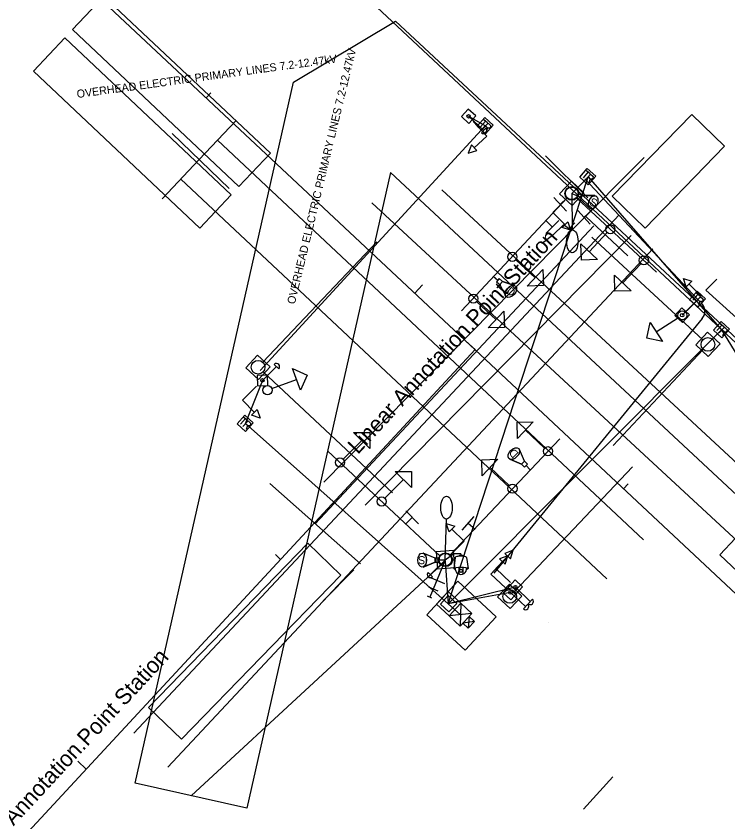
# Model space of a CAD drawing. Extents: x 1470334 to 1482043, y 378207 to 388330.
# Drawn here: x 1480096 to 1480220.4, y 379336.3 to 379477.2 of the extents above; entities that cross this region are included whole.
import ezdxf

# ---------------------------------------------------------------- set-up
doc = ezdxf.new("R2010")
doc.units = 0
for name, color, linetype in [('Default', 7, 'Continuous'), ('DR_X_Ditch', 7, 'Continuous'), ('DT_X_TIN_Hull', 7, 'Continuous'), ('GK_Visualization', 7, 'Continuous'), ('LT_X_Poles', 7, 'Continuous'), ('PM_X_Cells', 7, 'Continuous'), ('PM_X_Stop_Line', 7, 'Continuous'), ('PM_X_Surveyed_Line', 7, 'Continuous'), ('PV_X_Driveway', 7, 'Continuous'), ('PV_X_Parking_Lot', 7, 'Continuous'), ('PV_X_Steps', 7, 'Continuous'), ('RD_X_Cells', 7, 'Continuous'), ('RS_Raster1', 7, 'Continuous'), ('SV_X_Break_Lines', 7, 'Continuous'), ('SV_X_Control_Cells_Found', 7, 'Continuous'), ('SV_X_Random_Point', 7, 'Continuous'), ('SV_X_Text_Elevation', 7, 'Continuous'), ('SV_X_Text_Name', 7, 'Continuous'), ('UT_X_Gas_Cells', 7, 'Continuous'), ('UT_X_Sanitary_Cells', 7, 'Continuous'), ('UT_X_Unknown_Cells', 7, 'Continuous'), ('VG_X_Cells', 7, 'Continuous'), ('VG_X_Flower_Bed', 7, 'Continuous')]:
    doc.layers.add(name, color=color, linetype=linetype)

msp = doc.modelspace()

# ---------------------------------------------------------------- linework, layer by layer
at = {"layer": 'Default'}
for p, q in [((1479566.69, 379989.53), (1480555.97, 379063.33)), ((1480129.2, 379462.89), (1480130.02, 379463.77)), ((1480165.7, 379428.72), (1480167.07, 379430.18)), ((1480176.23, 379418.85), (1480174.77, 379420.21)), ((1480040.24, 379272.2), (1480176.23, 379418.85)), ((1480202.2, 379394.54), (1480203.02, 379395.42)), ((1480142.24, 379382.19), (1480141.36, 379383.01)), ((1480189.09, 379371.13), (1480189.09, 379371.13)), ((1480108.24, 379345.53), (1480106.77, 379346.89)), ((1480200.31, 379344.17), (1480195.21, 379338.53))]:
    msp.add_line(p, q, dxfattribs=at)
at = {"layer": 'DR_X_Ditch'}
for p, q in [((1480195.46, 379448.71), (1480215.13, 379427.66)), ((1480193.15, 379446.17), (1480193.15, 379446.17)), ((1480212.46, 379424.87), (1480215.19, 379427.6)), ((1480215.13, 379427.66), (1480215.13, 379427.66)), ((1480215.97, 379424.3), (1480179.5, 379379.76)), ((1480211.81, 379424.41), (1480207.93, 379421.93)), ((1480212.46, 379424.87), (1480212.46, 379424.87)), ((1480140.69, 379412.05), (1480145, 379413.66))]:
    msp.add_line(p, q, dxfattribs=at)
for points in [[(1480192.3, 379445.32), (1480189.82, 379442.85), (1480191.94, 379440.73)], [(1480213.31, 379425.72), (1480215.79, 379428.19), (1480213.67, 379430.32)], [(1480215.21, 379428.48), (1480214.32, 379427.49)], [(1480214.9, 379428.76), (1480215.52, 379428.21)], [(1480214.74, 379427.11), (1480215.63, 379428.11), (1480216, 379427.77), (1480216.04, 379427.73), (1480216.08, 379427.66), (1480216.09, 379427.63), (1480216.1, 379427.59), (1480216.09, 379427.52), (1480216.08, 379427.46), (1480216.04, 379427.39), (1480215.96, 379427.29), (1480215.92, 379427.27), (1480215.86, 379427.24), (1480215.78, 379427.21), (1480215.73, 379427.21), (1480215.69, 379427.22), (1480215.67, 379427.22), (1480215.64, 379427.24), (1480215.56, 379427.29), (1480215.19, 379427.62)], [(1480215.56, 379427.29), (1480215.32, 379426.59)]]:
    msp.add_lwpolyline(points, dxfattribs=at)
for points in [[(1480191.45, 379440.23), (1480192.44, 379441.22), (1480192.93, 379439.73)], [(1480214.17, 379430.81), (1480213.18, 379429.82), (1480212.68, 379431.31)], [(1480215.05, 379429.07), (1480216.54, 379427.74), (1480215.21, 379426.25), (1480213.72, 379427.58)], [(1480211.19, 379424.83), (1480212.5, 379423.6), (1480213.73, 379424.92), (1480212.42, 379426.15)], [(1480209.01, 379420.25), (1480206.25, 379420.85), (1480206.86, 379423.62)], [(1480144.3, 379415.53), (1480146.87, 379414.36), (1480145.7, 379411.79)]]:
    msp.add_lwpolyline(points, close=True, dxfattribs=at)
for centre, radius in [((1480212.48, 379424.84), 0.8), ((1480212.46, 379424.87), 0.3), ((1480139.94, 379411.77), 0.8)]:
    msp.add_circle(centre, radius, dxfattribs=at)
msp.add_arc((1480214.43, 379425.57), 2, 320.6881, 45.2385, dxfattribs=at)
at = {"layer": 'DT_X_TIN_Hull'}
for p, q in [((1480183.31, 379377.31), (1480171.52, 379374.44)), ((1480183.27, 379377.34), (1480183.27, 379377.34)), ((1480183.29, 379377.32), (1480185.89, 379374.83)), ((1480186.28, 379375.24), (1480185.5, 379374.43))]:
    msp.add_line(p, q, dxfattribs=at)
for points in [[(1480181.45, 379383.24), (1480182.46, 379382.27), (1480182.93, 379383.77)], [(1480183.33, 379376.05), (1480184.56, 379377.37), (1480183.25, 379378.6), (1480182.02, 379377.28)]]:
    msp.add_lwpolyline(points, close=True, dxfattribs=at)
msp.add_lwpolyline([(1480182.41, 379378.17), (1480179.88, 379380.59), (1480181.96, 379382.76)], dxfattribs=at)
msp.add_circle((1480183.29, 379377.32), 0.3, dxfattribs=at)
msp.add_arc((1480185.89, 379374.83), 0.56, 226.2141, 46.2138, dxfattribs=at)
at = {"layer": 'GK_Visualization'}
for points in [[(1480193.23, 379444.05), (1480195.27, 379446.24), (1480193.08, 379448.29), (1480191.03, 379446.09)], [(1480138.13, 379414.35), (1480138.19, 379412.55), (1480139.99, 379412.61), (1480139.93, 379414.41)], [(1480172.68, 379380.76), (1480172.44, 379383.75), (1480169.45, 379383.5), (1480169.69, 379380.51)], [(1480182.5, 379375.12), (1480183.71, 379376.45), (1480182.37, 379377.66), (1480181.16, 379376.33)]]:
    msp.add_lwpolyline(points, close=True, dxfattribs=at)
for centre, radius in [((1480193.15, 379446.17), 1.2), ((1480139.06, 379413.48), 0.3), ((1480171.07, 379382.13), 1.2), ((1480182.43, 379376.39), 0.3)]:
    msp.add_circle(centre, radius, dxfattribs=at)
at = {"layer": 'PM_X_Cells'}
for p, q in [((1480199.34, 379439.32), (1480196.2, 379435.96)), ((1480183.35, 379434.53), (1480186.73, 379431.4)), ((1480205.2, 379433.87), (1480202.06, 379430.51)), ((1480176.52, 379427.23), (1480179.89, 379424.11)), ((1480138.88, 379413.31), (1480138.88, 379413.31)), ((1480188.4, 379401.64), (1480185.04, 379404.78)), ((1480153.18, 379399.7), (1480156.41, 379402.97)), ((1480182.21, 379395.1), (1480178.86, 379398.25)), ((1480160.47, 379392.88), (1480163.7, 379396.15)), ((1480170.99, 379382.04), (1480170.99, 379382.04)), ((1480182.42, 379376.4), (1480182.42, 379376.4))]:
    msp.add_line(p, q, dxfattribs=at)
for points in [[(1480197.66, 379434.6), (1480194.83, 379434.5), (1480194.74, 379437.33)], [(1480188.08, 379432.87), (1480188.19, 379430.05), (1480185.37, 379429.94)], [(1480203.52, 379429.15), (1480200.69, 379429.05), (1480200.6, 379431.88)], [(1480181.25, 379425.57), (1480181.36, 379422.75), (1480178.53, 379422.64)], [(1480137.17, 379407.37), (1480138.16, 379408.36), (1480138.66, 379406.87)], [(1480183.68, 379403.32), (1480183.59, 379406.15), (1480186.41, 379406.24)], [(1480154.99, 379404.37), (1480157.81, 379404.39), (1480157.83, 379401.56)], [(1480177.49, 379396.79), (1480177.4, 379399.61), (1480180.23, 379399.7)], [(1480162.27, 379397.55), (1480165.1, 379397.57), (1480165.12, 379394.75)], [(1480172.7, 379387.98), (1480171.7, 379386.99), (1480171.21, 379388.48)], [(1480180.5, 379382.28), (1480181.53, 379381.32), (1480181.97, 379382.83)]]:
    msp.add_lwpolyline(points, close=True, dxfattribs=at)
for points in [[(1480138.03, 379412.46), (1480135.55, 379409.99), (1480137.67, 379407.86)], [(1480171.84, 379382.89), (1480174.32, 379385.36), (1480172.2, 379387.49)], [(1480181.54, 379377.22), (1480178.97, 379379.6), (1480181.01, 379381.8)]]:
    msp.add_lwpolyline(points, dxfattribs=at)
for centre in [(1480199.89, 379439.9), (1480182.76, 379435.07), (1480205.75, 379434.45), (1480175.93, 379427.77), (1480188.98, 379401.09), (1480152.62, 379399.13), (1480182.79, 379394.55), (1480159.91, 379392.31)]:
    msp.add_circle(centre, 0.8, dxfattribs=at)
at = {"layer": 'PM_X_Stop_Line'}
msp.add_line((1480193.15, 379446.17), (1480193.2, 379439.77), dxfattribs=at)
msp.add_ellipse((1480193.24, 379437.77), major_axis=(0, -2), ratio=0.5, dxfattribs=at)
at = {"layer": 'PM_X_Surveyed_Line'}
msp.add_line((1480005.18, 379622.84), (1480577.77, 379086.76), dxfattribs=at)
at = {"layer": 'PV_X_Driveway'}
for p, q in [((1480171.52, 379374.44), (1480196.02, 379449.05)), ((1480193.15, 379446.17), (1480195.93, 379448.95)), ((1480196.02, 379449.05), (1480219.33, 379422.34)), ((1480171.52, 379374.44), (1480219.33, 379422.34)), ((1480219.33, 379422.34), (1480224.91, 379413.13)), ((1480136.09, 379405.92), (1480139.1, 379413.52)), ((1480171.52, 379374.44), (1480136.04, 379405.97)), ((1480170.99, 379381.85), (1480171.52, 379374.44)), ((1480182.44, 379376.38), (1480171.52, 379374.44)), ((1480173.69, 379372.51), (1480171.52, 379374.44))]:
    msp.add_line(p, q, dxfattribs=at)
at = {"layer": 'PV_X_Parking_Lot'}
for p, q in [((1480195.95, 379449.09), (1480195.95, 379449.09)), ((1480219.33, 379422.34), (1480219.33, 379422.34)), ((1480136.04, 379405.97), (1480136.04, 379405.97))]:
    msp.add_line(p, q, dxfattribs=at)
for points in [[(1480195.87, 379450.5), (1480197.36, 379449.17), (1480196.03, 379447.68), (1480194.54, 379449.01)], [(1480219.26, 379423.76), (1480220.75, 379422.42), (1480219.41, 379420.93), (1480217.92, 379422.27)], [(1480135.96, 379407.39), (1480137.45, 379406.05), (1480136.11, 379404.56), (1480134.62, 379405.9)]]:
    msp.add_lwpolyline(points, close=True, dxfattribs=at)
for points in [[(1480196.03, 379449.91), (1480195.14, 379448.91)], [(1480195.56, 379448.54), (1480196.45, 379449.53), (1480196.82, 379449.2), (1480196.86, 379449.16), (1480196.9, 379449.09), (1480196.91, 379449.05), (1480196.92, 379449.02), (1480196.91, 379448.95), (1480196.9, 379448.89), (1480196.86, 379448.81), (1480196.78, 379448.72), (1480196.74, 379448.7), (1480196.68, 379448.66), (1480196.6, 379448.64), (1480196.55, 379448.64), (1480196.51, 379448.65), (1480196.49, 379448.65), (1480196.46, 379448.67), (1480196.38, 379448.72), (1480196.01, 379449.05)], [(1480195.72, 379450.19), (1480196.34, 379449.63)], [(1480196.38, 379448.72), (1480196.15, 379448.02)], [(1480219.42, 379423.16), (1480218.53, 379422.17)], [(1480218.95, 379421.8), (1480219.84, 379422.79), (1480220.21, 379422.45), (1480220.24, 379422.41), (1480220.28, 379422.35), (1480220.29, 379422.31), (1480220.3, 379422.27), (1480220.3, 379422.21), (1480220.29, 379422.15), (1480220.25, 379422.07), (1480220.16, 379421.98), (1480220.13, 379421.95), (1480220.07, 379421.92), (1480219.99, 379421.89), (1480219.94, 379421.9), (1480219.9, 379421.9), (1480219.88, 379421.91), (1480219.85, 379421.92), (1480219.77, 379421.98), (1480219.4, 379422.31)], [(1480219.11, 379423.44), (1480219.72, 379422.89)], [(1480219.77, 379421.98), (1480219.53, 379421.27)], [(1480136.12, 379406.79), (1480135.23, 379405.8)], [(1480135.65, 379405.43), (1480136.54, 379406.42), (1480136.91, 379406.08), (1480136.94, 379406.04), (1480136.98, 379405.98), (1480136.99, 379405.94), (1480137, 379405.9), (1480137, 379405.84), (1480136.99, 379405.78), (1480136.95, 379405.7), (1480136.86, 379405.61), (1480136.83, 379405.58), (1480136.77, 379405.55), (1480136.69, 379405.52), (1480136.64, 379405.53), (1480136.6, 379405.53), (1480136.58, 379405.54), (1480136.55, 379405.55), (1480136.47, 379405.61), (1480136.1, 379405.94)], [(1480135.81, 379407.07), (1480136.43, 379406.52)], [(1480136.47, 379405.61), (1480136.23, 379404.9)]]:
    msp.add_lwpolyline(points, dxfattribs=at)
at = {"layer": 'PV_X_Steps'}
for p, q in [((1480192.2, 379443.06), (1480190.04, 379445.43)), ((1480191.12, 379444.24), (1480192.3, 379445.32)), ((1480196.38, 379440.81), (1480194.22, 379443.18)), ((1480195.3, 379441.99), (1480196.48, 379443.07)), ((1480190.9, 379441.4), (1480188.63, 379439.15)), ((1480189.77, 379440.27), (1480188.64, 379441.41)), ((1480164.11, 379390.65), (1480166.37, 379388.38)), ((1480165.24, 379389.52), (1480164.11, 379388.39)), ((1480173.97, 379387.31), (1480176.09, 379389.71)), ((1480175.03, 379388.51), (1480176.23, 379387.45))]:
    msp.add_line(p, q, dxfattribs=at)
at = {"layer": 'RD_X_Cells'}
msp.add_line((1480170.99, 379382.04), (1480171.23, 379389.22), dxfattribs=at)
for centre in [(1480193.15, 379446.17), (1480171.04, 379382.12)]:
    msp.add_circle(centre, 1.1, dxfattribs=at)
msp.add_ellipse((1480171.24, 379391.22), major_axis=(0.01, 2), ratio=0.5, dxfattribs=at)
at = {"layer": 'RS_Raster1'}
for p, q in [((1480170.99, 379382.04), (1480168.31, 379375.58)), ((1480168.15, 379379.11), (1480170.92, 379377.96)), ((1480168.09, 379377.4), (1480169.75, 379376.71)), ((1480168.67, 379375.42), (1480167.94, 379375.73))]:
    msp.add_line(p, q, dxfattribs=at)
at = {"layer": 'SV_X_Break_Lines'}
for p, q in [((1480218.5, 379431.17), (1480216.59, 379429.25)), ((1480216.59, 379429.25), (1480241.59, 379406.51))]:
    msp.add_line(p, q, dxfattribs=at)
at = {"layer": 'SV_X_Control_Cells_Found'}
for p, q in [((1480148.26, 379388.42), (1480197.02, 379440.5)), ((1480140.34, 379395.44), (1480156.18, 379381.4))]:
    msp.add_line(p, q, dxfattribs=at)
msp.add_lwpolyline([(1480205.81, 379452.44), (1480193.1, 379439.67), (1480191.7, 379440.66), (1480189.86, 379438.85), (1480187.98, 379437.39)], dxfattribs=at)
at = {"layer": 'SV_X_Random_Point'}
for p, q in [((1480173.85, 379425.61), (1480192.3, 379445.32)), ((1480194.03, 379445.35), (1480207.94, 379432.41)), ((1480195.64, 379442.04), (1480202.97, 379435.23)), ((1480171.8, 379382.93), (1480191.04, 379403.27)), ((1480170.15, 379382.74), (1480150.43, 379401.17))]:
    msp.add_line(p, q, dxfattribs=at)
at = {"layer": 'SV_X_Text_Elevation'}
for p, q in [((1480134.45, 379458.9), (1480127.99, 379452.07)), ((1480123.26, 379456.62), (1480133.23, 379447.04)), ((1480131.22, 379455.48), (1480205.72, 379385.61)), ((1480188.55, 379452.76), (1480195.96, 379445.38)), ((1480127.99, 379452.07), (1480121.54, 379445.24)), ((1480124.77, 379448.66), (1480199.27, 379378.78)), ((1480232.78, 379389.02), (1480170.4, 379446.76)), ((1480197.6, 379444.2), (1480149.78, 379395.71)), ((1480229.26, 379378.73), (1480158.19, 379444.5)), ((1480201.41, 379442.44), (1480116.57, 379351.81)), ((1480203.51, 379438.79), (1480157, 379391.64)), ((1480207.35, 379436.5), (1480122.51, 379345.88))]:
    msp.add_line(p, q, dxfattribs=at)
at = {"layer": 'SV_X_Text_Name'}
for p, q in [((1480175.11, 379459.64), (1480175.11, 379459.64)), ((1480175.11, 379459.64), (1480177.74, 379457.19)), ((1480175.11, 379459.64), (1480178.07, 379457.95)), ((1480178.01, 379457.99), (1480138.65, 379415.22)), ((1480178.01, 379457.99), (1480178.01, 379457.99)), ((1480178.13, 379457.59), (1480177.36, 379456.78)), ((1480196.66, 379438.53), (1480216.07, 379420.59)), ((1480139.11, 379416.64), (1480159.05, 379437.7)), ((1480216.13, 379418.9), (1480200.41, 379402.11)), ((1480161.82, 379393.79), (1480139.17, 379414.95)), ((1480183.13, 379376.58), (1480203.75, 379398.38)), ((1480155.05, 379380.34), (1480149.7, 379374.96))]:
    msp.add_line(p, q, dxfattribs=at)
for points in [[(1480175.17, 379458.37), (1480176.38, 379459.7), (1480175.05, 379460.91), (1480173.84, 379459.58)], [(1480177.93, 379459.41), (1480179.42, 379458.07), (1480178.08, 379456.58), (1480176.6, 379457.92)], [(1480176.56, 379453.64), (1480175.61, 379454.67), (1480175.06, 379453.21)], [(1480217.02, 379417.65), (1480219.07, 379419.85), (1480216.87, 379421.89), (1480214.83, 379419.7)], [(1480138.37, 379413.65), (1480140.41, 379415.84), (1480138.22, 379417.89), (1480136.17, 379415.69)], [(1480182.39, 379373.59), (1480184.43, 379375.78), (1480182.24, 379377.83), (1480180.19, 379375.63)]]:
    msp.add_lwpolyline(points, close=True, dxfattribs=at)
for points in [[(1480175.92, 379458.76), (1480178.29, 379456.18), (1480176.09, 379454.15)], [(1480178.09, 379458.81), (1480177.2, 379457.82)], [(1480177.62, 379457.45), (1480178.51, 379458.44), (1480178.88, 379458.1), (1480178.91, 379458.06), (1480178.96, 379458), (1480178.96, 379457.96), (1480178.97, 379457.92), (1480178.97, 379457.86), (1480178.96, 379457.8), (1480178.92, 379457.72), (1480178.83, 379457.63), (1480178.8, 379457.6), (1480178.74, 379457.57), (1480178.66, 379457.54), (1480178.61, 379457.55), (1480178.57, 379457.55), (1480178.55, 379457.56), (1480178.52, 379457.57), (1480178.44, 379457.63), (1480178.07, 379457.96)], [(1480177.78, 379459.09), (1480178.4, 379458.54)], [(1480178.44, 379457.63), (1480178.2, 379456.92)]]:
    msp.add_lwpolyline(points, dxfattribs=at)
for centre, radius in [((1480175.11, 379459.64), 0.3), ((1480216.95, 379419.77), 1.2), ((1480138.29, 379415.77), 1.2), ((1480182.31, 379375.71), 1.2)]:
    msp.add_circle(centre, radius, dxfattribs=at)
msp.add_arc((1480177.74, 379457.19), 0.56, 226.9499, 46.9495, dxfattribs=at)
at = {"layer": 'UT_X_Gas_Cells'}
for p, q in [((1480193.15, 379446.17), (1480194.13, 379445.76)), ((1480194.97, 379445.82), (1480194.68, 379445.12)), ((1480194.97, 379445.82), (1480197.19, 379445.78)), ((1480197.19, 379445.78), (1480194.97, 379445.82)), ((1480194.68, 379445.12), (1480196.26, 379443.57)), ((1480194.68, 379445.12), (1480196.26, 379443.57)), ((1480179.43, 379431.68), (1480180.23, 379430.98)), ((1480181.04, 379430.78), (1480180.55, 379430.21)), ((1480180.55, 379430.21), (1480181.04, 379430.78)), ((1480180.55, 379430.21), (1480181.56, 379428.23)), ((1480180.55, 379430.21), (1480181.56, 379428.23)), ((1480181.04, 379430.78), (1480183.14, 379430.05)), ((1480183.14, 379430.05), (1480181.04, 379430.78)), ((1480138.94, 379413.36), (1480141.51, 379415.88)), ((1480141.12, 379416.28), (1480141.9, 379415.48)), ((1480184.88, 379399.38), (1480183.99, 379401.41)), ((1480184.88, 379399.38), (1480183.99, 379401.41)), ((1480184.35, 379398.84), (1480182.3, 379399.7)), ((1480182.3, 379399.7), (1480184.35, 379398.84)), ((1480184.35, 379398.84), (1480184.88, 379399.38)), ((1480184.88, 379399.38), (1480184.35, 379398.84)), ((1480185.9, 379397.84), (1480185.15, 379398.58)), ((1480169.25, 379382.42), (1480167.19, 379383.26)), ((1480169.25, 379382.42), (1480167.19, 379383.26)), ((1480170.99, 379382.04), (1480168.42, 379379.52)), ((1480169.24, 379381.67), (1480169.25, 379382.42)), ((1480171.06, 379382.04), (1480170, 379382.05)), ((1480170.99, 379381.79), (1480170.99, 379382.29)), ((1480172.77, 379382.53), (1480172.52, 379380.57)), ((1480173.77, 379383.17), (1480173.77, 379382.92)), ((1480174.77, 379382.53), (1480175.02, 379380.57)), ((1480169.24, 379381.67), (1480167.18, 379380.85)), ((1480167.18, 379380.85), (1480169.24, 379381.67)), ((1480173.42, 379380.76), (1480173.42, 379379.63)), ((1480174.12, 379380.76), (1480174.12, 379379.63)), ((1480168.81, 379379.12), (1480168.02, 379379.92)), ((1480182.43, 379376.39), (1480185.07, 379373.94)), ((1480185.45, 379374.35), (1480184.69, 379373.53))]:
    msp.add_line(p, q, dxfattribs=at)
for points in [[(1480134.96, 379447.39), (1480140.45, 379453.21), (1480111.34, 379480.65), (1480105.86, 379474.82)], [(1480128.1, 379440.11), (1480133.59, 379445.93), (1480104.48, 379473.37), (1480099, 379467.55)], [(1480200.23, 379445.66), (1480205.97, 379440.09), (1480219.87, 379454.4), (1480214.13, 379459.98)], [(1480194.28, 379446.1), (1480193.99, 379445.41), (1480194.68, 379445.12), (1480194.97, 379445.82)], [(1480180.48, 379431.27), (1480179.99, 379430.7), (1480180.55, 379430.21), (1480181.04, 379430.78)], [(1480184.88, 379398.32), (1480185.41, 379398.85), (1480184.88, 379399.38), (1480184.35, 379398.84)], [(1480248.12, 379355.55), (1480253.61, 379361.37), (1480224.5, 379388.81), (1480219.02, 379382.99)], [(1480119.14, 379356.31), (1480124.88, 379350.74), (1480152.75, 379379.43), (1480147.01, 379385)], [(1480169.99, 379381.67), (1480170, 379382.42), (1480169.25, 379382.42), (1480169.24, 379381.67)]]:
    msp.add_lwpolyline(points, close=True, dxfattribs=at)
for points in [[(1480194.28, 379446.1), (1480193.99, 379445.41), (1480194.68, 379445.12), (1480194.97, 379445.82), (1480194.28, 379446.1)], [(1480181.04, 379430.78), (1480180.48, 379431.27), (1480179.99, 379430.7), (1480180.55, 379430.21)], [(1480184.35, 379398.84), (1480184.88, 379398.32), (1480185.41, 379398.85), (1480184.88, 379399.38)], [(1480169.99, 379381.67), (1480170, 379382.42), (1480169.25, 379382.42), (1480169.24, 379381.67), (1480169.99, 379381.67)], [(1480173.77, 379383.17), (1480172.52, 379383.17), (1480170.99, 379382.04)], [(1480173.52, 379382.72), (1480173.52, 379382.92), (1480174.02, 379382.92), (1480174.02, 379382.72)]]:
    msp.add_lwpolyline(points, dxfattribs=at)
msp.add_circle((1480173.77, 379380.18), 0.273, dxfattribs=at)
for centre, radius, start, end in [((1480141.51, 379415.88), 0.56, 314.4065, 134.4061), ((1480173.77, 379380.57), 1, 173.0175, 6.9825), ((1480168.42, 379379.52), 0.56, 134.4065, 314.4061), ((1480185.07, 379373.94), 0.56, 227.1442, 47.1439)]:
    msp.add_arc(centre, radius, start, end, dxfattribs=at)
for centre, major_axis in [((1480196.89, 379444.6), (-0.48, -1.14)), ((1480182.49, 379429.02), (-0.812, -0.936)), ((1480183.02, 379400.69), (0.87, 0.883)), ((1480167, 379382.06), (0, 1.24))]:
    msp.add_ellipse(centre, major_axis=major_axis, ratio=0.621318, dxfattribs=at)
for centre, major_axis, ratio, start_param, end_param in [((1480196.89, 379444.6), (-0.48, -1.14), 0.621318, 3.386213, 6.038231), ((1480182.49, 379429.02), (-0.812, -0.936), 0.621318, 3.386213, 6.038231), ((1480183.02, 379400.69), (0.87, 0.883), 0.621318, 3.386213, 6.038231), ((1480167, 379382.06), (0, 1.24), 0.621318, 3.386213, 6.038231), ((1480173.77, 379382.53), (1, 0), 0.2, 0, 3.141593), ((1480173.77, 379380.57), (1.25, 0), 0.16, 5.62986, 10.078104)]:
    msp.add_ellipse(centre, major_axis=major_axis, ratio=ratio, start_param=start_param, end_param=end_param, dxfattribs=at)
at = {"layer": 'UT_X_Sanitary_Cells'}
for p, q in [((1480173.74, 379374.52), (1480173.65, 379370.5)), ((1480175.69, 379372.7), (1480171.7, 379372.32)), ((1480175.22, 379372.2), (1480175.03, 379370.16)), ((1480176.13, 379371.35), (1480174.12, 379371.01))]:
    msp.add_line(p, q, dxfattribs=at)
for points in [[(1480173.24, 379378.39), (1480167.8, 379372.52), (1480174.51, 379366.29), (1480179.95, 379372.16)], [(1480171.54, 379376.56), (1480169.5, 379374.36), (1480171.7, 379372.32), (1480173.74, 379374.52)], [(1480171.56, 379375.85), (1480170.2, 379374.38), (1480171.67, 379373.02), (1480173.03, 379374.49)], [(1480173.74, 379374.52), (1480175.69, 379372.7), (1480173.65, 379370.5), (1480171.7, 379372.32)], [(1480175.22, 379372.2), (1480176.13, 379371.35), (1480175.03, 379370.16), (1480174.12, 379371.01)]]:
    msp.add_lwpolyline(points, close=True, dxfattribs=at)
at = {"layer": 'UT_X_Unknown_Cells'}
for p, q in [((1480192.64, 379439.92), (1480193.71, 379441)), ((1480192.99, 379439.56), (1480194.08, 379440.65))]:
    msp.add_line(p, q, dxfattribs=at)
at = {"layer": 'VG_X_Cells'}
for p, q in [((1480144.5, 379465.58), (1480162.34, 379476.3)), ((1480162.34, 379476.3), (1480254.13, 379390.77)), ((1480116.83, 379343.08), (1480144.5, 379465.58)), ((1480161.44, 379449.8), (1480136.34, 379338.67)), ((1480240.5, 379376.14), (1480161.44, 379449.8)), ((1480136.34, 379338.67), (1480116.83, 379343.08))]:
    msp.add_line(p, q, dxfattribs=at)
at = {"layer": 'VG_X_Flower_Bed'}
msp.add_line((1480126.59, 379340.87), (1480170.99, 379381.87), dxfattribs=at)

# ---------------------------------------------------------------- texts
at = {"layer": 'Default'}
for p in [(1480155.74, 379400.43), (1480087.74, 379327.1)]:
    msp.add_text('Linear Annotation.Point Station', height=2.8, rotation=47.1589, dxfattribs=at).set_placement(p)
at = {"layer": 'LT_X_Poles'}
for rotation, p in [(76.4634, (1480144.71, 379426.7)), (7.7723, (1480106.68, 379462.83))]:
    msp.add_text('OVERHEAD ELECTRIC PRIMARY LINES 7.2-12.47kV', height=1.4, rotation=rotation, dxfattribs=at).set_placement(p)
at = {"layer": 'UT_X_Gas_Cells'}
for s, rotation, p in [('S', 337.309, (1480196.12, 379444.17)), ('D', 319.0977, (1480181.56, 379428.9)), ('D', 135.4331, (1480183.96, 379400.74)), ('S', 179.8426, (1480167.55, 379382.75))]:
    msp.add_text(s, height=1.4, rotation=rotation, dxfattribs=at).set_placement(p)

doc.saveas('drawing.dxf')
